(* Logix 5000 project; controller PLX51HART4O_Example 1756-L63 rev 16.22; software revision 16.04 *)

TASK MainTask (continuous, watchdog 500 ms) : MainProgram

MODULES
   Local : 1756-L63 (ICP 0, rev 16.22)
      EN2T_107 : 1756-EN2T (ICP 6, Ethernet 192.168.0.107, rev 1.3)
         PLX51HART4O : ETHERNET-MODULE (Ethernet 192.168.0.45, rev 1.1, Output RPI 200 ms)
END_MODULES

TYPE HART4Input :
STRUCT
   Instance : ProsoftSTRING16;
   ConfigurationStatus : HARTModuleStatus;
   Temperature : REAL;
   Ch0_ManufacturerID : SINT;
   Ch0_ManufacturerDeviceType : SINT;
   Ch0_DeviceID : DINT;
   Ch0_Tag : ProsoftSTRING8;
   Ch0_Descriptor : ProsoftSTRING16;
   Ch0_DeviceStatus : HARTDeviceStatus;
   Ch0_HARTStatus : HARTStatus;
   Ch0_RawCurrent : REAL;
   Ch0_ScaledValue : REAL;
   Ch0_DigitialCurrent : REAL;
   Ch0_PV : REAL;
   Ch0_SV : REAL;
   Ch0_TV : REAL;
   Ch0_FV : REAL;
   Ch0_PVUnitCode : SINT;
   Ch0_SVUnitCode : SINT;
   Ch0_TVUnitCode : SINT;
   Ch0_FVUnitCode : SINT;
   Ch0_Diagnostics : HARTDiagnostics;
   Ch1_ManufacturerID : SINT;
   Ch1_ManufacturerDeviceType : SINT;
   Ch1_DeviceID : DINT;
   Ch1_Tag : ProsoftSTRING8;
   Ch1_Descriptor : ProsoftSTRING16;
   Ch1_DeviceStatus : HARTDeviceStatus;
   Ch1_HARTStatus : HARTStatus;
   Ch1_RawCurrent : REAL;
   Ch1_ScaledValue : REAL;
   Ch1_DigitialCurrent : REAL;
   Ch1_PV : REAL;
   Ch1_SV : REAL;
   Ch1_TV : REAL;
   Ch1_FV : REAL;
   Ch1_PVUnitCode : SINT;
   Ch1_SVUnitCode : SINT;
   Ch1_TVUnitCode : SINT;
   Ch1_FVUnitCode : SINT;
   Ch1_Diagnostics : HARTDiagnostics;
   Ch2_ManufacturerID : SINT;
   Ch2_ManufacturerDeviceType : SINT;
   Ch2_DeviceID : DINT;
   Ch2_Tag : ProsoftSTRING8;
   Ch2_Descriptor : ProsoftSTRING16;
   Ch2_DeviceStatus : HARTDeviceStatus;
   Ch2_HARTStatus : HARTStatus;
   Ch2_RawCurrent : REAL;
   Ch2_ScaledValue : REAL;
   Ch2_DigitialCurrent : REAL;
   Ch2_PV : REAL;
   Ch2_SV : REAL;
   Ch2_TV : REAL;
   Ch2_FV : REAL;
   Ch2_PVUnitCode : SINT;
   Ch2_SVUnitCode : SINT;
   Ch2_TVUnitCode : SINT;
   Ch2_FVUnitCode : SINT;
   Ch2_Diagnostics : HARTDiagnostics;
   Ch3_ManufacturerID : SINT;
   Ch3_ManufacturerDeviceType : SINT;
   Ch3_DeviceID : DINT;
   Ch3_Tag : ProsoftSTRING8;
   Ch3_Descriptor : ProsoftSTRING16;
   Ch3_DeviceStatus : HARTDeviceStatus;
   Ch3_HARTStatus : HARTStatus;
   Ch3_RawCurrent : REAL;
   Ch3_ScaledValue : REAL;
   Ch3_DigitialCurrent : REAL;
   Ch3_PV : REAL;
   Ch3_SV : REAL;
   Ch3_TV : REAL;
   Ch3_FV : REAL;
   Ch3_PVUnitCode : SINT;
   Ch3_SVUnitCode : SINT;
   Ch3_TVUnitCode : SINT;
   Ch3_FVUnitCode : SINT;
   Ch3_Diagnostics : HARTDiagnostics;
END_STRUCT
END_TYPE

TYPE HART4Output :
STRUCT
   Channel_0 : REAL;
   Channel_1 : REAL;
   Channel_2 : REAL;
   Channel_3 : REAL;
END_STRUCT
END_TYPE

TYPE HARTDeviceStatus :
STRUCT
   LoopOpen : BOOL;
   CurrentUnderrange : BOOL;
   CurrentOverrange : BOOL;
   LoopShorted : BOOL;
   CalibrationBusy : BOOL;
   CalibrationFaulted : BOOL;
   HARTCommsFault : BOOL;
   RelayMessagesInhibited : BOOL;
END_STRUCT
END_TYPE

TYPE HARTDiagnostics :
STRUCT
   DeviceSpecificStatus0_0 : SINT;
   DeviceSpecificStatus0_1 : SINT;
   DeviceSpecificStatus0_2 : SINT;
   DeviceSpecificStatus0_3 : SINT;
   DeviceSpecificStatus0_4 : SINT;
   DeviceSpecificStatus0_5 : SINT;
   Reserved0 : SINT;
   Reserved1 : SINT;
   OperationMode_0 : SINT;
   OperationMode_1 : SINT;
   Reserved2 : SINT;
   Reserved3 : SINT;
   StandardizedStatus0 : SINT;
   StandardizedStatus1 : SINT;
   AnalogChannelSaturated : SINT;
   StandardizedStatus2 : SINT;
   StandardizedStatus3 : SINT;
   AnalogChannelFixed : SINT;
   DeviceSpecific1_0 : SINT;
   DeviceSpecific1_1 : SINT;
   DeviceSpecific1_2 : SINT;
   DeviceSpecific1_3 : SINT;
   DeviceSpecific1_4 : SINT;
   DeviceSpecific1_5 : SINT;
   DeviceSpecific1_6 : SINT;
   DeviceSpecific1_7 : SINT;
   DeviceSpecific1_8 : SINT;
   DeviceSpecific1_9 : SINT;
   DeviceSpecific1_10 : SINT;
END_STRUCT
END_TYPE

TYPE HARTMessageRequest :
STRUCT
   Length : INT;
   StartCharacter : SINT;   // (0x82 for Long Address)
   AddressByte0 : SINT;   // (0x80 + Manufacturer ID)
   AddressByte1 : SINT;   // (Device Type Code)
   AddressByte2 : SINT;   // (Device ID Byte 0)
   AddressByte3 : SINT;   // (Device ID Byte 1)
   AddressByte4 : SINT;   // (Device ID Byte 2)
   CommandData : SINT[40];
END_STRUCT
END_TYPE

TYPE HARTMessageResponse :
STRUCT
   Status : INT;
   PacketLength : INT;
   StartCharacter : SINT;
   AddressByte0 : SINT;
   AddressByte1 : SINT;
   AddressByte2 : SINT;
   AddressByte3 : SINT;
   AddressByte4 : SINT;
   Command : SINT;
   ByteCount : SINT;
   Data : SINT[50];
END_STRUCT
END_TYPE

TYPE HARTModuleStatus :
STRUCT
   ConfigurationValid : BOOL;
   Channel0Enabled : BOOL;
   Channel1Enabled : BOOL;
   Channel2Enabled : BOOL;
   Channel3Enabled : BOOL;
   Channel0HARTEnabled : BOOL;
   Channel1HARTEnabled : BOOL;
   Channel2HARTEnabled : BOOL;
   Channel3HARTEnabled : BOOL;
END_STRUCT
END_TYPE

TYPE HARTStatus :
STRUCT
   ParityError : BOOL;
   OverrunError : BOOL;
   FramingError : BOOL;
   ChecksumError : BOOL;
   RxBufferOverflow : BOOL;
   ValueTooLarge : BOOL;
   ValueTooSmall : BOOL;
   NotEnoughBytesInCommand : BOOL;
   TransmitterSpecificCmdError : BOOL;
   InWriteProtectMode : BOOL;
   UpdateFailed : BOOL;
   AppliedProcessTooHigh : BOOL;
   AppliedProcessTooLow : BOOL;
   InMultidropMode : BOOL;
   InvalidUnitCode : BOOL;
   BothRangeValuesOutOfLimits : BOOL;
   PushedUpperRangeValueOverLimit : BOOL;
   AccessRestricted : BOOL;
   DeviceBusy : BOOL;
   CommandNotImplemented : BOOL;
   DeviceMalfunction : BOOL;
   ConfigurationChanged : BOOL;
   Coldstart : BOOL;
   MoreStatusAvailable : BOOL;
   LoopCurrentFixed : BOOL;
   LoopCurrentSaturated : BOOL;
   NonPrimaryVariableOutOFLimits : BOOL;
   PrimaryVariableOutOfLimites : BOOL;
END_STRUCT
END_TYPE

TYPE Input :
STRUCT
   Data : HART4Input;
END_STRUCT
END_TYPE

TYPE MessageControl :
STRUCT
   TriggerMessage : BOOL;
   MessageRequest : HARTMessageRequest;
   MessageResponse : HARTMessageResponse;
END_STRUCT
END_TYPE

TYPE Output :
STRUCT
   Data : HART4Output;
END_STRUCT
END_TYPE

TYPE PLX51HART4O_MODULEDEF :
STRUCT
   Input : Input;   // Data Read from End Device
   Output : Output;   // Data Written to End Device
   Control : MessageControl;   // Message to be sent to End Device
END_STRUCT
END_TYPE

TYPE ProsoftSTRING16 :   // string type
STRUCT
   LEN : DINT;
   DATA : SINT[16];
END_STRUCT
END_TYPE

TYPE ProsoftSTRING8 :   // string type
STRUCT
   LEN : DINT;
   DATA : SINT[8];
END_STRUCT
END_TYPE

VAR_GLOBAL   (* controller tags *)
   HARTMessage : MESSAGE;
        MessageParameters(ServiceCode := 16#0079, LocalElement := PLX51HART.Control.MessageRequest, DestinationTag := PLX51HART.Control.MessageResponse, ...)
   PLX51HART : PLX51HART4O_MODULEDEF;
END_VAR

PROGRAM MainProgram   (* main routine MainRoutine *)

ROUTINE MainRoutine   (* ladder *)
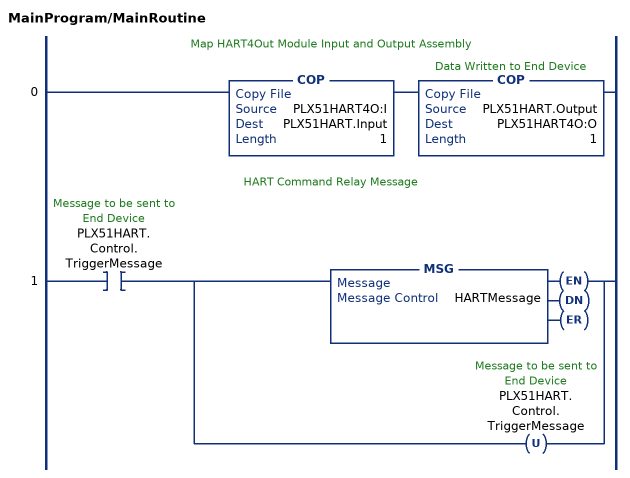
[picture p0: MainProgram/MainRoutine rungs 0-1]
   // Map HART4Out Module Input and Output Assembly
   0: COP(PLX51HART4O:I,PLX51HART.Input,1)COP(PLX51HART.Output,PLX51HART4O:O,1);
   // HART Command Relay Message
   1: XIC(PLX51HART.Control.TriggerMessage)[MSG(HARTMessage) ,OTU(PLX51HART.Control.TriggerMessage) ];
END_ROUTINE
END_PROGRAM
